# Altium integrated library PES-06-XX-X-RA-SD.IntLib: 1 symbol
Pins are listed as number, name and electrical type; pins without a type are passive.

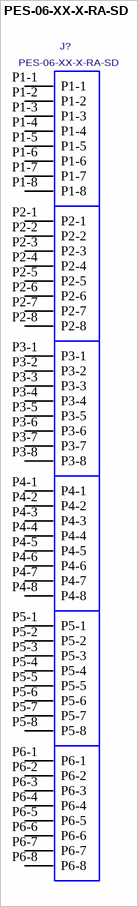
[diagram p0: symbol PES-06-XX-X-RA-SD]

## PES-06-XX-X-RA-SD
designator J?
RIGHT ANGLE POWER SOCKET.; MANUFACTURER: SAMTEC
footprint PES-06-XX-X-RA-SD
pins: P1-1, P1-2, P1-3, P1-4, P1-5, P1-6, P1-7, P1-8, P2-1, P2-2, P2-3, P2-4, P2-5, P2-6, P2-7, P2-8, P3-1, P3-2, P3-3, P3-4, P3-5, P3-6, P3-7, P3-8, P4-1, P4-2, P4-3, P4-4, P4-5, P4-6, P4-7, P4-8, P5-1, P5-2, P5-3, P5-4, P5-5, P5-6, P5-7, P5-8, P6-1, P6-2, P6-3, P6-4, P6-5, P6-6, P6-7, P6-8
